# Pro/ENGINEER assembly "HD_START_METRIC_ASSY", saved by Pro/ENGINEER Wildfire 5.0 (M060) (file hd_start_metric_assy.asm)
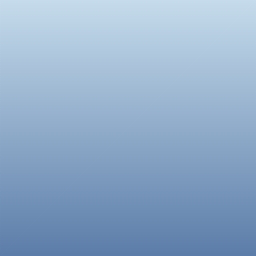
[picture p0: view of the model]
Units: hd_metric; MM, KILOGRAM, SECS

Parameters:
  DRW_UNITS = "METRIC"
  TOL_NAME = "MILLIMETERS"
  SUR = "6.3"
  LINEAR_TOL_0 = "1.0"

Other named items: ASIDE, ATOP, AFRONT, ACS_DEF, APT_ORIG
